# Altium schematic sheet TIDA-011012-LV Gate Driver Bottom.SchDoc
size 431 x 279 mm; Date: Not shown in title block; ApprovedBy: Not shown in title block; CheckedBy: Not shown in title block; Author: Not shown in title block; CompanyName: Not shown in title block; Engineer: Not shown in title block; Organization: Not shown in title block; Address1: Not shown in title block; Address2: Not shown in title block; Address3: Not shown in title block; Address4: Not shown in title block; DocumentNumber: 1; Revision: Use project parameter SCH_Rev; SheetNumber: 1; SheetTotal: 1; PageSetup: Record=PageOptions¦CenterHorizontal=True¦CenterVertical=True¦PrintScale=1.00¦XCorrection=1.00¦YCorrection=1.00¦PrintKind=0¦BorderSize=5000000¦LeftOffset=0¦BottomOffset=0¦Orientation=2¦PaperLength=1000¦PaperWidth=1000¦Scale=100¦PaperSource=15¦PrintQuality=600¦MediaType=1¦DitherType=10¦PaperKind=Letter¦PrintScaleMode=1
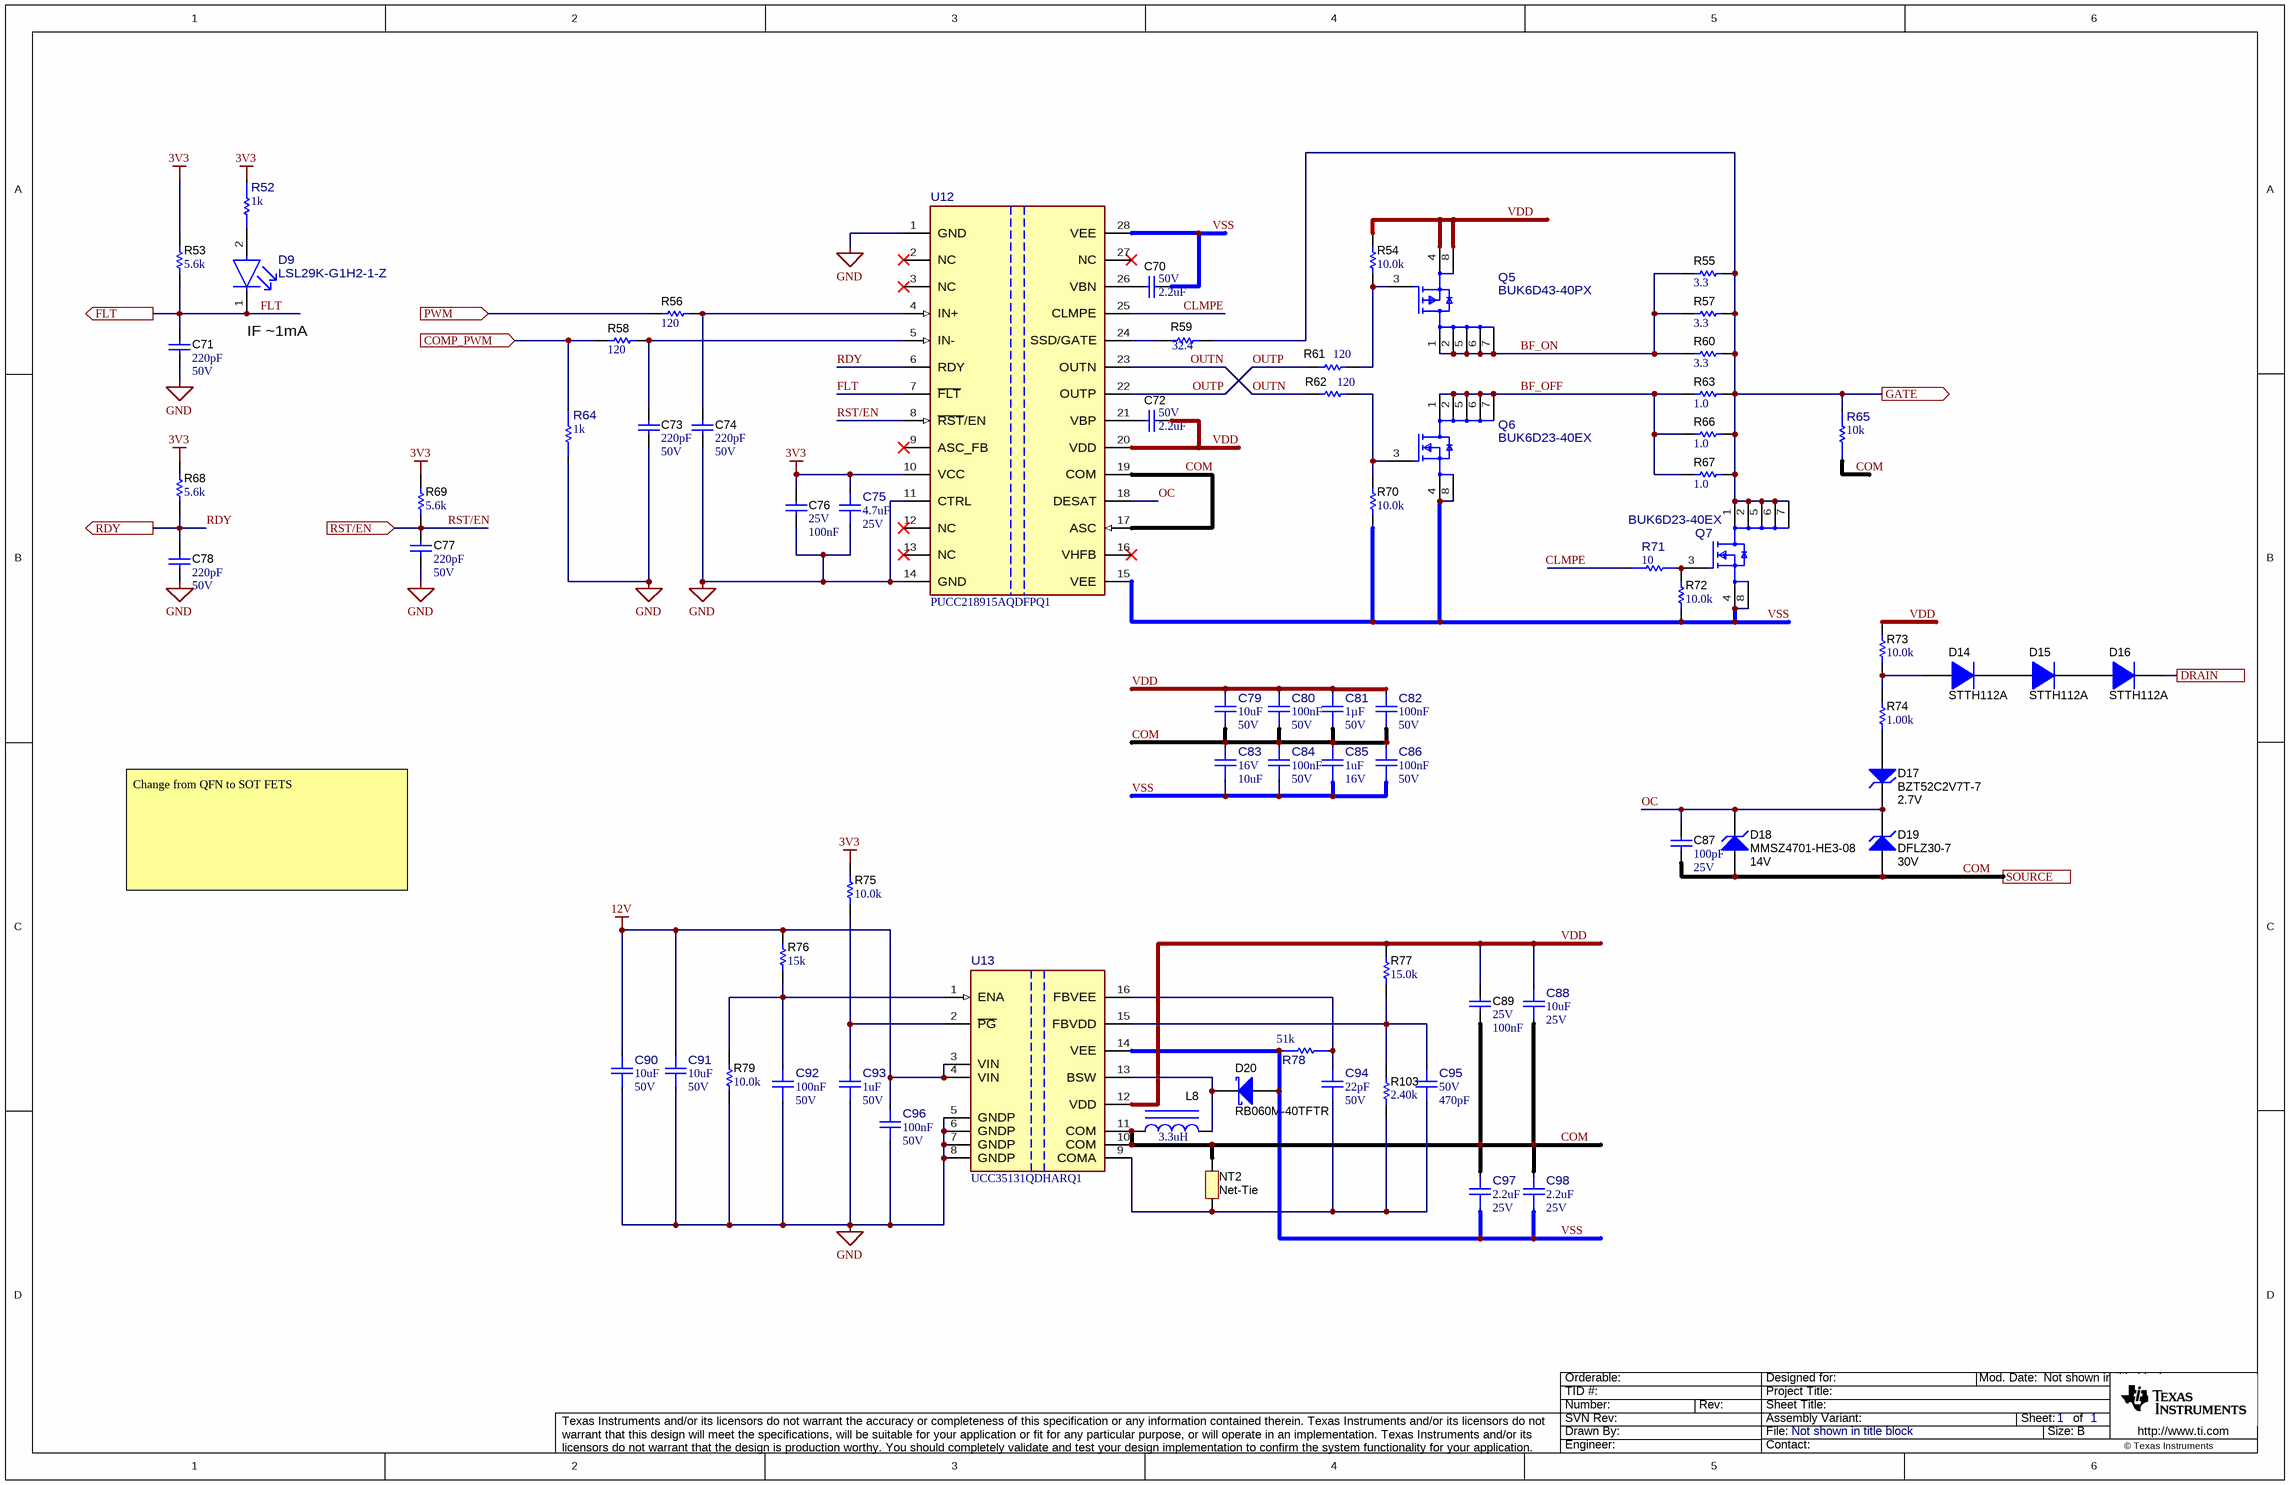
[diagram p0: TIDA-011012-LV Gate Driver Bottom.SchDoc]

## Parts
C70  VDC_V: 50V  ValueDisplayed: 2.2uF  [0603]  (hidden comment: GRT188R61H225KE13D)
C71  Cap_F: 220pF  VDC_V: 50V  [0603]  (hidden comment: C0603C221K5RACTU)
C72  VDC_V: 50V  ValueDisplayed: 2.2uF  [0603]  (hidden comment: GRT188R61H225KE13D)
C73  Cap_F: 220pF  VDC_V: 50V  [0603]  (hidden comment: C0603C221K5RACTU)
C74  Cap_F: 220pF  VDC_V: 50V  [0603]  (hidden comment: C0603C221K5RACTU)
C75  ValueDisplayed: 4.7uF  VDC_V: 25V  [FP-GRM188R61E475KE15D_0603-MFG]  (hidden comment: GRM188R61E475KE15D)
C76  VDC_V: 25V  Cap_F: 100nF  [0603]  (hidden comment: GCM188R71E104KA57D)
C77  Cap_F: 220pF  VDC_V: 50V  [0603]  (hidden comment: C0603C221K5RACTU)
C78  Cap_F: 220pF  VDC_V: 50V  [0603]  (hidden comment: C0603C221K5RACTU)
C79  ValueDisplayed: 10uF  VDC_V: 50V  [FP-GMC31X7R106K50NT_1206-MFG]  (hidden comment: GMC31X7R106K50NT)
C80  Cap_F: 100nF  VDC_V: 50V  [FP-C0805C104K5RAC7800_0805-MFG]  (hidden comment: C0805C104K5RAC7800)
C81  Cap_F: 1µF  VDC_V: 50V  [FP-CL10B105KB9VPJC_0603-MFG]  (hidden comment: CL10B105KB9VPJC)
C82  Cap_F: 100nF  VDC_V: 50V  [FP-C0603C104K5RAC3121_0603-MFG]  (hidden comment: C0603C104K5RAC3121)
C83  VDC_V: 16V  ValueDisplayed: 10uF  [FP-C1206C106J4RACAUTO_1206-MFG]  (hidden comment: C1206C106J4RACAUTO)
C84  Cap_F: 100nF  VDC_V: 50V  [FP-C0805C104K5RAC7800_0805-MFG]  (hidden comment: C0805C104K5RAC7800)
C85  ValueDisplayed: 1uF  VDC_V: 16V  [FP-GRM188C71C105KA12D_0603-MFG]  (hidden comment: GRM188C71C105KA12D)
C86  Cap_F: 100nF  VDC_V: 50V  [FP-C0603C104K5RAC3121_0603-MFG]  (hidden comment: C0603C104K5RAC3121)
C87  Cap_F: 100pF  VDC_V: 25V  [0603]  (hidden comment: 06033C101KAT2A)
C88  ValueDisplayed: 10uF  VDC_V: 25V  [FP-KGM31HR71E106KU_1206-MFG]  (hidden comment: KGM31HR71E106KU)
C89  VDC_V: 25V  Cap_F: 100nF  [0603]  (hidden comment: GCM188R71E104KA57D)
C90  ValueDisplayed: 10uF  VDC_V: 50V  [FP-GMC31X7R106K50NT_1206-MFG]  (hidden comment: GMC31X7R106K50NT)
C91  ValueDisplayed: 10uF  VDC_V: 50V  [FP-GMC31X7R106K50NT_1206-MFG]  (hidden comment: GMC31X7R106K50NT)
C92  Cap_F: 100nF  VDC_V: 50V  [FP-KGM15BR71H104JT_0603-MFG]  (hidden comment: KGM15BR71H104JT)
C93  ValueDisplayed: 1uF  VDC_V: 50V  [FP-C1206C105J5RECAUTO_1206-MFG]  (hidden comment: C1206C105J5RECAUTO)
C94  ValueDisplayed: 22pF  VDC_V: 50V  [FP-VJ0603D220JLAAJ32_0603-IPC_C]  (hidden comment: VJ0603D220JLAAJ32)
C95  VDC_V: 50V  ValueDisplayed: 470pF  [FP-C0603X471F5GACTU_0603-MFG]  (hidden comment: C0603X471F5GACTU)
C96  Cap_F: 100nF  VDC_V: 50V  [FP-KGM15BR71H104JT_0603-MFG]  (hidden comment: KGM15BR71H104JT)
C97  ValueDisplayed: 2.2uF  VDC_V: 25V  [FP-GRT188C71E225KE13D_0603-MFG]  (hidden comment: GRT188C71E225KE13D)
C98  ValueDisplayed: 2.2uF  VDC_V: 25V  [FP-CGA5L2X7R1E225K160AA_1206-MFG]  (hidden comment: CGA5L2X7R1E225K160AA)
D9  LSL29K-G1H2-1-Z  [FP-LSL29K-G1H2-1-Z_0603-0]
D14  STTH112A  [SMA]
D15  STTH112A  [SMA]
D16  STTH112A  [SMA]
D17  BZT52C2V7T-7  value 2.7V  [SOD-523]
D18  MMSZ4701-HE3-08  value 14V  [SOD-123]
D19  DFLZ30-7  value 30V  [PowerDI123]
D20  RB060M-40TFTR  [SOD-123]
L8  ValueDisplayed: 3.3uH  [0603]  (hidden comment: AIML-0603-3R3K-T)
NT2  Net-Tie  [Net-Tie_0805_HV_NoOverlay]  (net tie, no BOM)
Q5  BUK6D43-40PX  [FP-BUK6D43-40PX_SOT1220-MFG]
Q6  BUK6D23-40EX  [FP-BUK6D23-40EX_SOT1220-MFG]
Q7  BUK6D23-40EX  [FP-BUK6D23-40EX_SOT1220-MFG]
R52  Res_ohm: 1k  [FP-ERJ-3GEYJ102V_0603-MFG]  (hidden comment: ERJ-3GEYJ102V)
R53  ValueDisplayed: 5.6k  [0603]  (hidden comment: RC0603JR-075K6L)
R54  ValueDisplayed: 10.0k  [0603]  (hidden comment: ERJ-3EKF1002V)
R55  ValueDisplayed: 3.3  [1206]  (hidden comment: CRCW12063R30JNEA)
R56  ValueDisplayed: 120  [0603]  (hidden comment: CRCW0603120RJNEA)
R57  ValueDisplayed: 3.3  [1206]  (hidden comment: CRCW12063R30JNEA)
R58  ValueDisplayed: 120  [0603]  (hidden comment: CRCW0603120RJNEA)
R59  ValueDisplayed: 32.4  [1206]  (hidden comment: CRCW120632R4FKEA)
R60  ValueDisplayed: 3.3  [1206]  (hidden comment: CRCW12063R30JNEA)
R61  ValueDisplayed: 120  [0603]  (hidden comment: RT0603BRD07120RL)
R62  ValueDisplayed: 120  [0603]  (hidden comment: RT0603BRD07120RL)
R63  ValueDisplayed: 1.0  [1206]  (hidden comment: CRM1206-JW-1R0ELF)
R64  Res_ohm: 1k  [FP-ERJ-3GEYJ102V_0603-MFG]  (hidden comment: ERJ-3GEYJ102V)
R65  value 10k  [FP-560112116005_0603-MFG]  (hidden comment: 560112116005)
R66  ValueDisplayed: 1.0  [1206]  (hidden comment: CRM1206-JW-1R0ELF)
R67  ValueDisplayed: 1.0  [1206]  (hidden comment: CRM1206-JW-1R0ELF)
R68  ValueDisplayed: 5.6k  [0603]  (hidden comment: RC0603JR-075K6L)
R69  ValueDisplayed: 5.6k  [0603]  (hidden comment: RC0603JR-075K6L)
R70  ValueDisplayed: 10.0k  [0603]  (hidden comment: ERJ-3EKF1002V)
R71  value 10  [FP-ESR03EZPF10R0_0603-MFG]  (hidden comment: ESR03EZPF10R0)
R72  ValueDisplayed: 10.0k  [0603]  (hidden comment: ERJ-3EKF1002V)
R73  ValueDisplayed: 10.0k  [0603]  (hidden comment: ERJ-3EKF1002V)
R74  ValueDisplayed: 1.00k  [0603]  (hidden comment: ERJ-3EKF1001V)
R75  ValueDisplayed: 10.0k  [0603]  (hidden comment: ERJ-3EKF1002V)
R76  ValueDisplayed: 15k  [0603]  (hidden comment: RC0603JR-0715KL)
R77  ValueDisplayed: 15.0k  [0603]  (hidden comment: RT0603BRD0715KL)
R78  value 51k  [FP-ERA-3AED513V_0603-MFG]  (hidden comment: ERA-3AED513V)
R79  ValueDisplayed: 10.0k  [0603]  (hidden comment: RT0603DRE0710KL)
R103  ValueDisplayed: 2.40k  [0603]  (hidden comment: RT0603DRE072K4L)
U12  PUCC218915AQDFPQ1  [DFP0028A-MFG]
U13  UCC35131QDHARQ1  [DHA0016A-MFG]

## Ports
COMP_PWM (in), DRAIN, FLT (out), GATE (out), PWM (in), RDY (out), RST/EN (in), SOURCE

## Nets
3V3: C75.2 C76.2 R52.1 R53.2 R68.2 R69.2 R75.2 U12.10(VCC)
12V: C90.2 C91.2 C96.2 R76.2 U13.3(VIN) U13.4(VIN)
GND: C71.2 C73.2 C74.2 C75.1 C76.1 C77.2 C78.2 C90.1 C91.1 C92.1 C93.1 C96.1 R64.2 R79.1 U12.1(GND) U12.11(CTRL) U12.14(GND) U13.5(GNDP) U13.6(GNDP) U13.7(GNDP) U13.8(GNDP)
BF_OFF: Q6.1(D) Q6.2(D) Q6.5(D) Q6.6(D) Q6.7(D) R63.1 R66.1 R67.1
BF_ON: Q5.1(D) Q5.2(D) Q5.5(D) Q5.6(D) Q5.7(D) R55.1 R57.1 R60.1
CLMPE: R71.1 U12.25(CLMPE)
COM: C79.1 C80.1 C81.1 C82.1 C83.2 C84.2 C85.2 C86.2 C87.2 C88.1 C89.2 C97.2 C98.2 D18.2(A) D19.2(A) L8.1 NT2.2 R65.1 U12.17(ASC) U12.19(COM) U13.10(COM) U13.11(COM) ; port SOURCE
COMP_PWM: R58.1 R64.1 ; port COMP_PWM
DRAIN: D16.1(K) ; port DRAIN
FLT: C71.1 D9.1(CATHODE) R53.1 U12.7(~{FLT}) ; port FLT
GATE: Q7.1(D) Q7.2(D) Q7.5(D) Q7.6(D) Q7.7(D) R55.2 R57.2 R59.2 R60.2 R63.2 R65.2 R66.2 R67.2 ; port GATE
OC: C87.1 D17.1(K) D18.1(K) D19.1(K) U12.18(DESAT)
OUTN: R62.1 U12.23(OUTN)
OUTP: R61.1 U12.22(OUTP)
PWM: R56.1 ; port PWM
RDY: C78.1 R68.1 U12.6(RDY) ; port RDY
RST/EN: C77.1 R69.1 U12.8(~{RST}/EN) ; port RST/EN
VDD: C72.1 C79.2 C80.2 C81.2 C82.2 C88.2 C89.1 Q5.4(S) Q5.8(S) R54.2 R73.2 R77.2 U12.20(VDD) U13.12(VDD)
VSS: C70.1 C83.1 C84.1 C85.1 C86.1 C97.1 C98.1 D20.2(A) Q6.4(S) Q6.8(S) Q7.4(S) Q7.8(S) R70.1 R72.1 R78.1 U12.15(VEE) U12.28(VEE) U13.14(VEE)
NetC70_2: C70.2 U12.26(VBN)
NetC72_2: C72.2 U12.21(VBP)
NetC73_1: C73.1 R58.2 U12.5(IN-)
NetC74_1: C74.1 R56.2 U12.4(IN+)
NetC92_2: C92.2 R76.1 R79.2 U13.1(ENA)
NetC93_2: C93.2 R75.1 U13.2(~{PG})
NetC94_1: C94.1 C95.1 NT2.1 R103.1 U13.9(COMA)
NetC94_2: C94.2 R78.2 U13.16(FBVEE)
NetC95_2: C95.2 R77.1 R103.2 U13.15(FBVDD)
NetD9_2: D9.2(ANODE) R52.2
NetD14_1: D14.1(K) D15.2(A)
NetD14_2: D14.2(A) R73.1 R74.2
NetD15_1: D15.1(K) D16.2(A)
NetD17_2: D17.2(A) R74.1
NetD20_1: D20.1(K) L8.2 U13.13(BSW)
NetQ5_3: Q5.3(G) R54.1 R61.2
NetQ6_3: Q6.3(G) R62.2 R70.2
NetQ7_3: Q7.3(G) R71.2 R72.2
NetR59_1: R59.1 U12.24(SSD/GATE)

Not connected (* = marked no-connect by the designer): U12 2(NC)* 3(NC)* 9(ASC_FB)* 12(NC)* 13(NC)* 16(VHFB)* 27(NC)*

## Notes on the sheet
- (near D9) IF
  mA
- Change from QFN to SOT FETS

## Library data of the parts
C70 C72 = CMP-0007502-5: CAP, CERM, 2.2 uF, 50 V, +/- 10%, X5R, AEC-Q200 Grade 3, 0603; Manufacturer: MuRata; TaMin_C: -55°C; Polarized: N; SizeAreaWB_mm2: 4.68; Value1: Unknown; U/M: EA; Value: 2.2uF; TaMax_C: 85°C; SizeZ_mm: 1; SizeX_mm: 1.6; SizeY_mm: 0.8; SizeArea_mm2: 1.28; AEC Qualified: Y; Cap_F: 2.2µF; AEC Grade: 3; AEC Category: Q200
C71 C73 C74 C77 C78 = CMP-0006895-4: CAP, CERM, 220 pF, 50 V, +/- 10%, X7R, 0603; Manufacturer: Kemet; TaMin_C: -55°C; Polarized: N; SizeAreaWB_mm2: 4.68; Value1: Unknown; U/M: EA; Value: 220pF; TaMax_C: 125°C; SizeZ_mm: 1; SizeX_mm: 1.6; SizeY_mm: 0.8; SizeArea_mm2: 1.28; AEC Category: Q200
C75 = CMP-0091702-1: 4.7µF ±10% 25V Ceramic Capacitor X5R 0603 (1608 Metric); Manufacturer: Murata; AEC Qualified: No; SizeZ_mm: 1mm; TempCo: 15%
C76 C89 = CMP-0084679-1: CAP, CERM, 0.1 µF, 25 V,+/- 10%, X7R, AEC-Q200 Grade 1, 0603; Manufacturer: MuRata; TaMin_C: -55°C; SizeY_mm: 0.8; Polarized: N; SizeArea_mm2: 1.28; SizeZ_mm: 1; SizeX_mm: 1.6; AEC Qualified: Y; AEC Category: Q200; Value: 0.1uF; ValueDisplayed: 0.1µF; TaMax_C: 125°C; U/M: EA; SizeAreaWB_mm2: 4.68
C79 C90 C91 = CMP-0093201-1: 10 µF ±10% 50V Ceramic Capacitor X7R 1206 (3216 Metric); Manufacturer: Cal-Chip Electronics; AEC Qualified: No; SizeZ_mm: 1.8mm; TempCo: 15%; Value: 10µF
C80 C84 = CMP-0120154-1: 0.1 µF ±10% 50V Ceramic Capacitor X7R 0805 (2012 Metric); Manufacturer: KEMET; AEC Qualified: No; SizeZ_mm: 0.88mm; TempCo: 15%; ValueDisplayed: 0.1uF; Value: 100nF
C81 = CMP-0122257-1: 1 µF ±10% 50V Ceramic Capacitor X7R 0603 (1608 Metric); Manufacturer: Samsung; AEC Grade: Grade 1; AEC Qualified: Yes; SizeZ_mm: 1mm; TempCo: 15%; ValueDisplayed: 1uF; Value: 1µF
C82 C86 = CMP-0093594-1: 0.1 µF ±10% 50V Ceramic Capacitor X7R 0603 (1608 Metric); Manufacturer: KEMET; AEC Grade: Grade 1; AEC Qualified: Yes; ValueDisplayed: 0.1uF; SizeZ_mm: 0.87mm; TempCo: 15%; Value: 100nF
C83 = CMP-0094514-1: 10 µF ±5% 16V Ceramic Capacitor X7R 1206 (3216 Metric); Manufacturer: KEMET; SizeZ_mm: 1.8mm; TempCo: 15%; Cap_F: 10µF; Value: 10µF; AEC Qualified: Yes; AEC Grade: Grade 1
C85 = CMP-0122429-1: 1 µF ±10% 16V Ceramic Capacitor X7S 0603 (1608 Metric); Manufacturer: Murata; AEC Qualified: No; Cap_F: 1µF; SizeZ_mm: 0.9mm; TempCo: 22%; Value: 1µF
C87 = CMP-0006751-4: CAP, CERM, 100 pF, 25 V, +/- 10%, X7R, 0603; Manufacturer: AVX; TaMin_C: -55°C; Polarized: N; SizeAreaWB_mm2: 4.68; Value1: Unknown; U/M: EA; Value: 100pF; TaMax_C: 125°C; SizeZ_mm: 1; SizeX_mm: 1.6; SizeY_mm: 0.8; SizeArea_mm2: 1.28; AEC Category: Q200
C88 = CMP-0044202-1: 10 µF ±10% 25V Ceramic Capacitor X7R 1206 (3216 Metric); Manufacturer: KYOCERA AVX; AEC Qualified: No; Cap_F: 10µF; SizeZ_mm: 1.9mm; TempCo: 15%; Value: 10µF
C92 C96 = CMP-0120061-1: 0.1 µF ±5% 50V Ceramic Capacitor X7R 0603 (1608 Metric); Manufacturer: KYOCERA AVX; AEC Qualified: No; SizeZ_mm: 0.94mm; TempCo: 15%; ValueDisplayed: 0.1uF; Value: 100nF
C93 = CMP-0094524-1: 1 µF ±5% 50V Ceramic Capacitor X7R 1206 (3216 Metric); Manufacturer: KEMET; TempCo: 15%; Cap_F: 1µF; AEC Grade: Grade 1; AEC Qualified: Yes; SizeZ_mm: 1.1mm; Value: 1µF
C94 = CMP-0039814-1: 22 pF ±5% 50V Ceramic Capacitor C0G, NP0 0603 (1608 Metric); Manufacturer: Vishay; AEC Grade: Grade 0; AEC Qualified: Yes; SizeZ_mm: 0.97mm; TempCo: 30ppm/°C; Value: 22pF
C95 = CMP-0097612-1: Cap Ceramic 470pF 50V C0G 1% SMD 0603 125°C Paper T/R; Manufacturer: KEMET; SizeZ_mm: 0.95mm; TempCo: 30ppm/°C; AEC Qualified: No
C97 = CMP-0125378-1: Multi-Layer Ceramic Capacitor 2.2uF 25V X7S ±10% 0603 Paper T/R; Manufacturer: Murata; AEC Grade: Grade 1; AEC Qualified: Yes; Cap_F: 2.2µF; SizeZ_mm: 1mm; TempCo: 22%; Value: 2.2µF
C98 = CMP-0090741-1: Cap Ceramic 2.2uF 25V X7R 10% Pad SMD 1206 +125°C Automotive T/R; Manufacturer: TDK; Cap_F: 2.2µF; Value: 2.2µF; Tolerance_%: 0.1%; TempCo: 15%; AEC Grade: Grade 1; AEC Qualified: Yes; SizeZ_mm: 1.9mm
D9 = CMP-0092845-1: LED Uni-Color Red 643nm 2-Pin Chip 0603(1608Metric) T/R; Manufacturer: OSRAM Opto Semiconductors; AEC Grade: Grade 2; LuminousFlux_PhiV: 8.1/16.1lm; Vf_V: 1.8V; Forward Current: 2mA; Led Orientation: Top View; SizeZ_mm: 0.67mm; AEC Qualified: Yes; Luminous Intensity: 1.8-2.24/3.55-4.5mcd; Vr_V: 12V; Angle: 160°; LambdaD: 630nm; Tjmax_C: 110°C
D14-D16 = CMP-0077081-2: Diode, Ultrafast, 1200 V, 1 A, SMA; Manufacturer: STMicroelectronics; AEC Qualified: N; TJmax_C: 175°C; SizeX_mm: 5.59; Green_Lifecycle: Not Set; Io_A: 1A; Value2: 1.9V; SizeY_mm: 2.92; SizeZ_mm: 2.87; AEC Category: Q101; Value: 1200V; SizeAreaWB_mm2: 37.3428; Vr_V: 1.2kV; Green_REACh: Incomplete; SizeArea_mm2: 16.3228
D17 = CMP-0005892-4: Diode, Zener, 2.7 V, 300 mW, SOD-523; Manufacturer: Diodes Inc.; SizeY_mm: 0.9; AEC Category: Q101; SizeX_mm: 1.7; Power_W: 300mW; Value1: 0.3W; SizeZ_mm: 0.65; SizeAreaWB_mm2: 5.13; RJA_CperW: 417; SizeArea_mm2: 1.53
D18 = CMP-0077574-3: Diode, Zener, 14 V, 500 mW, AEC-Q101, SOD-123; Manufacturer: Vishay-Semiconductor; Power_W: 500mW; Value1: 0.5W; AEC Qualified: Y; SizeZ_mm: 1.35; SizeAreaWB_mm2: 13.095; SizeX_mm: 3.85; AEC Category: Q101; RJA_CperW: 340; SizeY_mm: 1.7; SizeArea_mm2: 6.545
D19 = CMP-0005417-4: Diode, Zener, 30 V, 1 W, PowerDI123; Manufacturer: Diodes Inc.; SizeX_mm: 3.7; Power_W: 1W; SizeY_mm: 1.78; AEC Category: Q101; RJA_CperW: 110; SizeArea_mm2: 6.586; SizeZ_mm: 0.98; SizeAreaWB_mm2: 13.066
D20 = CMP-0028628-2: Diode, Schottky, 40 V, 2 A, SOD-123; Manufacturer: Rohm; Green_REACh: Incomplete; SizeX_mm: 3.85; SizeZ_mm: 1.35; TJmax_C: 150°C; Value1: 2A; SizeAreaWB_mm2: 13.095; SizeArea_mm2: 6.545; AEC Category: Q101; Value2: 0.56V; SizeY_mm: 1.7; Value: 40V; Vf_V: 560mV; Green_Lifecycle: Not Set
L8 = CMP-0059575-1: Inductor, Multilayer, Ferrite, 3.3 uH, 0.015 A, 1.55 ohm, SMD; Manufacturer: Abracon Corporation; Green_Lifecycle: Active; SizeAreaWB_mm2: 4.68; DCR_ohm: 1.55; Green_REACh: Passed; Value: 3.3uH; Imax_A: 15mA; SizeZ_mm: 1; SizeX_mm: 1.6; SizeY_mm: 0.8; Value2: 0.015A; SizeArea_mm2: 1.28; Ind_H: 3.3µH; AEC Qualified: N; AEC Category: Q200
NT2 = CMP-0078142-6: Single point connection between nets.
Q5 = CMP-0120257-1: P-Channel 40 V 6A (Ta) 15W (Tc) Surface Mount DFN2020MD-6; Manufacturer: Nexperia; AEC Qualified: Yes; IdsMax_A: -6A; QgTyp_nC: 24nC @ -10V; Rdson45_ohm: 30m; SizeZ_mm: 0.65mm; VdsMax_V: -1.2V; Vgs_V: 20V; ChMode: False; AEC Grade: Grade 0; Drain To Source Breakdown Voltage: -40V; Input Capacitace At Vds: 1260pF @ -20V; Number Of Channels: 1; Power_W: 2.3W; Pulse Drain Current: -56A; Reverse Recovery Charge: 8nC; Reverse Recovery Time: 15.6ns; Rthja Max: 57K/W; TaMax_C: +175°C; TaMin_C: -55°C; Threshold Vgs Max: -2.7V; Threshold Vgs Min: -1.4V; Transconductance: 33S; Turn Off Delay Time: 35ns; Turn On Delay Time: 9ns; Typ Forward Diode Voltage: -0.8V
Q6 Q7 = CMP-0120256-1: N-Channel 40 V 8A (Ta), 19A (Tc) 2.3W (Ta), 15W (Tc) Surface Mount DFN2020MD-6; Manufacturer: Nexperia; AEC Qualified: Yes; QgTyp_nC: 11nC @ 10V; Rdson45_ohm: 17m; SizeZ_mm: 0.65mm; VdsMax_V: 1.2V; Vgs_V: 20V; ChMode: False; AEC Grade: Grade 0; Drain To Source Breakdown Voltage: 40V; Input Capacitace At Vds: 582pF @ 20V; Number Of Channels: 1; Pulse Drain Current: 76A; Reverse Recovery Charge: 5.4nC; Reverse Recovery Time: 12.8ns; Rthja Max: 57K/W; TaMax_C: +175°C; TaMin_C: -55°C; Threshold Vgs Max: 2.7V; Threshold Vgs Min: 1.3V; Transconductance: 33S; Turn Off Delay Time: 12ns; Turn On Delay Time: 2ns; Typ Forward Diode Voltage: 0.8V
R52 R64 = CMP-0089144-1: 1 kOhms ±5% 0.1W, 1/10W Chip Resistor 0603 (1608 Metric) Automotive AEC-Q200 Thick Film; Manufacturer: Panasonic; Power_W: 100mW; AEC Qualified: Yes; Voltage: 75V; AEC Grade: Grade 0; SizeZ_mm: 0.55mm; TempCo: 200ppm/°C
R53 R68 R69 = CMP-0025933-5: RES, 5.6 k, 5%, 0.1 W, 0603; Manufacturer: Yageo; Power_W: 100mW; TempCo: 100 ppm/C; Value_Code: 5k60; Value: 5.6k; EIA_Code: E24; SizeX_mm: 1.6; SizeY_mm: 0.8; SizeZ_mm: 1; Value2: 0.1W; SizeArea_mm2: 1.28; AEC Qualified: N; VDC_V: 75V; AEC Category: Q200; SizeAreaWB_mm2: 4.68
R54 R70 R72 R73 R75 = CMP-0022684-3: RES, 10.0 k, 1%, 0.1 W, 0603; Manufacturer: Panasonic; Power_W: 100mW; TempCo: 100 ppm/C; Value_Code: 10k0; U/M: EA; Value: 10.0k; EIA_Code: E96; Res_ohm: 10k; SizeX_mm: 1.6; SizeY_mm: 0.8; SizeZ_mm: 1; Value2: 0.1W; SizeArea_mm2: 1.28; VDC_V: 75V; AEC Category: Q200
R55 R57 R60 = CMP-0018677-3: RES, 3.3, 5%, 0.25 W, AEC-Q200 Grade 0, 1206; Manufacturer: Vishay-Dale; Power_W: 250mW; TempCo: 200 ppm/C; Value_Code: 3R30; Value: 3.3; EIA_Code: E24; SizeX_mm: 3.2; SizeY_mm: 1.6; SizeZ_mm: 1.35; Value2: 0.25W; SizeArea_mm2: 5.12; AEC Qualified: Y; VDC_V: 200V; AEC Category: Q200; AEC Grade: 0
R56 R58 = CMP-0025710-4: RES, 120, 5%, 0.1 W, AEC-Q200 Grade 0, 0603; Manufacturer: Vishay-Dale; Power_W: 100mW; TempCo: 200 ppm/C; Value_Code: 120R; Value: 120; EIA_Code: E24; SizeX_mm: 1.6; SizeY_mm: 0.8; SizeZ_mm: 1; Value2: 0.1W; SizeArea_mm2: 1.28; AEC Qualified: Y; VDC_V: 75V; AEC Category: Q200; AEC Grade: 0
R59 = CMP-0016910-3: RES, 32.4, 1%, 0.25 W, AEC-Q200 Grade 0, 1206; Manufacturer: Vishay-Dale; Power_W: 250mW; TempCo: 100 ppm/C; Value_Code: 32R4; Value: 32.4; EIA_Code: E96; SizeX_mm: 3.2; SizeY_mm: 1.6; SizeZ_mm: 1.35; Value2: 0.25W; SizeArea_mm2: 5.12; AEC Qualified: Y; VDC_V: 200V; AEC Category: Q200; AEC Grade: 0
R61 R62 = CMP-0023691-3: RES, 120, 0.1%, 0.1 W, 0603; Manufacturer: Yageo America; Power_W: 100mW; TempCo: 25 ppm/C; Value_Code: 120R; U/M: EA; Value: 120; EIA_Code: E192; SizeX_mm: 1.6; SizeY_mm: 0.8; SizeZ_mm: 1; Value2: 0.1W; SizeArea_mm2: 1.28; VDC_V: 75V; AEC Category: Q200
R63 R66 R67 = CMP-0018745-2: RES, 1.0, 5%, 0.5 W, 1206; Manufacturer: Bourns; Power_W: 500mW; TempCo: 150 ppm/C; Value_Code: 1R00; U/M: EA; Value: 1.0; EIA_Code: E24; Res_ohm: 1; SizeX_mm: 3.2; SizeY_mm: 1.6; SizeZ_mm: 1.35; Value2: 0.5W; SizeArea_mm2: 5.12; VDC_V: 1V; AEC Category: Q200
R65 = CMP-0125815-1: 10 kOhms ±1% 0.1W, 1/10W Chip Resistor 0603 (1608 Metric) Anti-Sulfur Thick Film; Manufacturer: Wurth Electronics; AEC Qualified: No; Power_W: 100mW; SizeZ_mm: 0.6mm; TempCo: 100ppm/°C; VDC_V: 75V
R71 = CMP-0094841-1: 10 Ohms ±1% 0.25W, 1/4W Chip Resistor 0603 (1608 Metric) Automotive AEC-Q200, Pulse Withstanding Thick Film; Manufacturer: ROHM; AEC Qualified: Yes; SizeZ_mm: 0.55mm; TempCo: 100ppm/°C; AEC Grade: Grade 0; Power_W: 250mW; VDC_V: 150V
R74 = CMP-0022680-4: RES, 1.00 k, 1%, 0.1 W, 0603; Manufacturer: Panasonic; Power_W: 100mW; TempCo: 100 ppm/C; Value_Code: 1k00; U/M: EA; Value: 1.00k; EIA_Code: E96; Res_ohm: 1k; SizeX_mm: 1.6; SizeY_mm: 0.8; SizeZ_mm: 1; SizeArea_mm2: 1.28; VDC_V: 75V; AEC Category: Q200; Value2: 0.1W
R76 = CMP-0025890-5: RES, 15 k, 5%, 0.1 W, 0603; Manufacturer: Yageo; Power_W: 100mW; TempCo: 100 ppm/C; Value_Code: 15k0; Value: 15k; EIA_Code: E24; SizeX_mm: 1.6; SizeY_mm: 0.8; SizeZ_mm: 1; Value2: 0.1W; SizeArea_mm2: 1.28; AEC Qualified: N; VDC_V: 75V; AEC Category: Q200; SizeAreaWB_mm2: 4.68
R77 = CMP-0023780-3: RES, 15.0 k, 0.1%, 0.1 W, 0603; Manufacturer: Yageo America; Power_W: 100mW; TempCo: 25 ppm/C; Value_Code: 15k0; U/M: EA; Value: 15.0k; EIA_Code: E192; Res_ohm: 15k; SizeX_mm: 1.6; SizeY_mm: 0.8; SizeZ_mm: 1; Value2: 0.1W; SizeArea_mm2: 1.28; VDC_V: 75V; AEC Category: Q200
R78 = CMP-0031881-1: 51 kOhms ±0.5% 0.1W, 1/10W Chip Resistor 0603 (1608 Metric) Automotive AEC-Q200 Thin Film; Manufacturer: Panasonic; AEC Grade: Grade 0; AEC Qualified: Yes; Power_W: 100mW; SizeZ_mm: 0.55mm; TempCo: 25ppm/°C; VDC_V: 75V
R79 = CMP-0024586-3: RES, 10.0 k, 0.5%, 0.1 W, 0603; Manufacturer: Yageo America; Power_W: 100mW; TempCo: 50 ppm/C; Value_Code: 10k0; U/M: EA; Value: 10.0k; EIA_Code: E192; Res_ohm: 10k; SizeX_mm: 1.6; SizeY_mm: 0.8; SizeZ_mm: 1; Value2: 0.1W; SizeArea_mm2: 1.28; VDC_V: 75V; AEC Category: Q200
R103 = CMP-0025064-3: RES, 2.40 k, 0.5%, 0.1 W, 0603; Manufacturer: Yageo America; Power_W: 100mW; TempCo: 50 ppm/C; Value_Code: 2k40; U/M: EA; Value: 2.40k; EIA_Code: E192; Res_ohm: 2.4k; SizeX_mm: 1.6; SizeY_mm: 0.8; SizeZ_mm: 1; Value2: 0.1W; SizeArea_mm2: 1.28; VDC_V: 75V; AEC Category: Q200
U12 = CMP-0128293-1: Single Channel Isolated Pre-Driver for SiC/IGBT with Active Protection; Manufacturer: Texas Instruments; SizeZ_mm: 2.6mm; AEC Qualified: Yes; AEC Grade: Grade 1; Max Supply Voltage: 28V; Min Supply Voltage: 3V; Number Of Drivers: 1; Standoff Height: 0.05mm; TaMax_C: +125°C; TaMin_C: -40°C; TJmax_C: +150°C; Turn Off Delay Time: 65ns
U13 = CMP-0126653-2: Automotive 2.0W, 12V VIN, High-Density, > 5kVRMS, Isolated DC/DC Module; Manufacturer: Texas Instruments; SizeZ_mm: 2.6mm; AEC Qualified: Yes; AEC Grade: Grade 1; Max Supply Voltage: 20V; Min Supply Voltage: 5.5V; Number Of Outputs: 2; Output Type: AdjustableProgrammable; Output Voltage: -2-8/12-18V; Standoff Height: 0.1mm; TaMax_C: +125°C; TaMin_C: -40°C; TJmax_C: +150°C; AEC Category: Q200; CompType: IC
